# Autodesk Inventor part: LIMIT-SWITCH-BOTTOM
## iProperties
Created: 2007-08
Part Number: LIMIT-SWITCH-BOTTOM
Material: ABS Plastic
Document SubType Name: Modeling
Density: 1.06 g/cm^3
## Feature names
1. Base1
